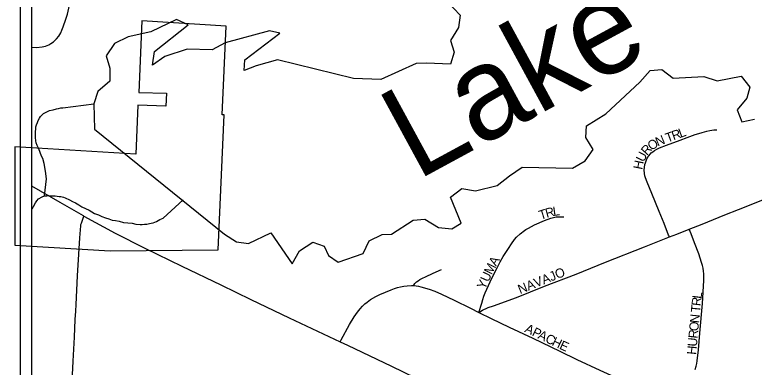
# Model space of a CAD drawing. Extents: x -5.4 to 49.9, y 13.2 to 48.4.
# Drawn here: x 26.26 to 27.015, y 42.652 to 43.012 of the extents above; entities that cross this region are included whole.
import ezdxf

# ---------------------------------------------------------------- set-up
doc = ezdxf.new("R2010")
doc.units = 0
for name, color, linetype in [('GM_X_Corporation', 7, 'Continuous'), ('GM_X_County_Road', 7, 'Continuous'), ('GM_X_Major_Lake', 7, 'Continuous'), ('GM_X_Major_Lake_Text', 7, 'Continuous'), ('GM_X_Major_River', 7, 'Continuous'), ('GM_X_Township', 7, 'Continuous'), ('GM_X_Township_Road', 7, 'Continuous'), ('GM_X_Township_Subdivision', 7, 'Continuous'), ('GM_X_Township_Subdivision_Text', 7, 'Continuous')]:
    doc.layers.add(name, color=color, linetype=linetype)

msp = doc.modelspace()

# ---------------------------------------------------------------- linework, layer by layer
at = {"layer": 'GM_X_Corporation'}
for p, q in [((26.26551, 43.78252), (26.26551, 42.05419)), ((26.25991, 42.87737), (26.25991, 42.77689))]:
    msp.add_line(p, q, dxfattribs=at)
msp.add_lwpolyline([(26.25991, 42.77689), (26.3573, 42.77098), (26.46771, 42.772), (26.47367, 42.91013), (26.47177, 42.91025), (26.47569, 43.00088), (26.38967, 43.0061), (26.38652, 42.93306), (26.41492, 42.93233), (26.41435, 42.91909), (26.38576, 42.91982), (26.3836, 42.86986), (26.25991, 42.87737)], dxfattribs=at)
at = {"layer": 'GM_X_County_Road'}
for points in [[(26.2771, 42.83744), (26.30605, 42.82085), (26.32962, 42.807), (26.33059, 42.80647)], [(26.33059, 42.80647), (26.36234, 42.78919), (26.39264, 42.77368), (26.43071, 42.75545), (26.47045, 42.73637), (26.5011, 42.72131), (26.54035, 42.70261), (26.59236, 42.67796)], [(26.59236, 42.67796), (26.59986, 42.6744), (26.64477, 42.65311), (26.6945, 42.62894), (26.73983, 42.6071), (26.78075, 42.58757), (26.80831, 42.57462), (26.83401, 42.56232), (26.85936, 42.55058), (26.87388, 42.54353), (26.90078, 42.53072), (26.9225, 42.51997), (26.93923, 42.51181), (26.97405, 42.49539), (27.03132, 42.46825), (27.06275, 42.45329), (27.11662, 42.42769), (27.1357, 42.41862), (27.15695, 42.4083), (27.18263, 42.39579), (27.20393, 42.38562), (27.21459, 42.38058), (27.23308, 42.37173), (27.23815, 42.36925)]]:
    msp.add_lwpolyline(points, dxfattribs=at)
at = {"layer": 'GM_X_Major_Lake'}
for points in [[(26.69535, 43.03297), (26.71498, 43.01205), (26.71318, 42.99956), (26.70492, 42.98608), (26.70883, 42.97424), (26.70514, 42.9618), (26.68053, 42.9631), (26.6699, 42.96257), (26.6339, 42.94629), (26.60587, 42.94728), (26.5282, 42.96645), (26.50645, 42.9601)], [(26.50645, 42.9601), (26.49421, 42.95544), (26.49484, 42.96643), (26.5307, 42.99372), (26.52013, 42.99585), (26.47475, 42.98357), (26.4617, 42.97664), (26.43594, 42.97721), (26.41302, 42.96975), (26.40069, 42.96091), (26.40252, 42.97491), (26.43687, 43.00224), (26.42524, 43.00743), (26.3988, 42.99511), (26.37556, 42.98993), (26.36176, 42.98302), (26.35313, 42.97031), (26.35702, 42.9577), (26.35711, 42.94442), (26.34474, 42.93407), (26.34067, 42.92125), (26.34123, 42.89544)], [(26.47418, 42.78815), (26.48652, 42.78029), (26.49861, 42.77851), (26.5216, 42.78938), (26.54326, 42.75779), (26.55076, 42.77091), (26.56422, 42.77972), (26.57588, 42.77567), (26.58022, 42.76608), (26.59031, 42.75941), (26.61591, 42.76833), (26.62188, 42.78111), (26.63529, 42.78764), (26.64478, 42.78819), (26.66671, 42.80251), (26.67886, 42.80338), (26.6927, 42.79473), (26.70632, 42.79367), (26.71592, 42.79915), (26.70514, 42.82595), (26.71671, 42.8348), (26.73068, 42.83222), (26.7528, 42.8378), (26.76515, 42.84777), (26.77824, 42.85659), (26.82977, 42.85546), (26.84245, 42.86315), (26.85067, 42.87473), (26.84336, 42.88704), (26.84401, 42.89879), (26.86362, 42.91126), (26.89846, 42.9435), (26.90896, 42.95541), (26.92073, 42.95629), (26.93229, 42.94769), (26.96379, 42.94928), (26.97734, 42.9448), (27.00209, 42.94957), (27.01094, 42.93837), (27.00765, 42.92706), (26.99791, 42.91513), (27.00256, 42.90289), (27.01552, 42.90564)], [(26.34123, 42.89544), (26.47418, 42.78815)]]:
    msp.add_lwpolyline(points, dxfattribs=at)
at = {"layer": 'GM_X_Major_River'}
for points in [[(26.29028, 42.82711), (26.29236, 42.84456), (26.29131, 42.85255), (26.28987, 42.86016), (26.28841, 42.86549), (26.28729, 42.86778), (26.28581, 42.8716), (26.28434, 42.87541), (26.28285, 42.87884), (26.28174, 42.88151), (26.28138, 42.88342), (26.28104, 42.88684), (26.28108, 42.89064), (26.28154, 42.89785), (26.28194, 42.89974), (26.2831, 42.90239), (26.28388, 42.90428), (26.28504, 42.90655), (26.2862, 42.90843), (26.28927, 42.91144), (26.29194, 42.91293), (26.29537, 42.91441), (26.29917, 42.91513), (26.3026, 42.91624), (26.3045, 42.9166), (26.30679, 42.91733), (26.30906, 42.91731), (26.34067, 42.92125)], [(26.2771, 42.81344), (26.27762, 42.81395), (26.27916, 42.81621), (26.2811, 42.81999), (26.28226, 42.82226), (26.28418, 42.82414), (26.288, 42.82638), (26.29028, 42.82711), (26.29256, 42.82709), (26.29484, 42.82744), (26.29674, 42.82742), (26.29901, 42.8274), (26.30129, 42.82738), (26.30318, 42.82698), (26.30508, 42.82658), (26.30698, 42.82656), (26.30962, 42.82577), (26.31152, 42.82537), (26.31567, 42.82305), (26.31869, 42.8215), (26.32209, 42.81994), (26.32548, 42.81801), (26.3285, 42.81608), (26.33605, 42.81258), (26.33869, 42.81103), (26.34133, 42.80911), (26.34549, 42.80792), (26.34888, 42.80599), (26.35267, 42.80481), (26.35607, 42.80363), (26.35947, 42.80246), (26.36288, 42.80204), (26.36667, 42.80124), (26.37083, 42.80006), (26.37538, 42.79963), (26.37993, 42.79921), (26.38372, 42.79841), (26.38789, 42.79798), (26.39017, 42.79796), (26.39245, 42.79832), (26.39473, 42.79829), (26.39739, 42.79902), (26.39929, 42.79938), (26.40119, 42.79974), (26.40462, 42.80085), (26.40806, 42.80309), (26.41149, 42.80457), (26.43189, 42.82302)]]:
    msp.add_lwpolyline(points, dxfattribs=at)
at = {"layer": 'GM_X_Township'}
msp.add_line((26.2771, 45.17828), (26.2771, 40.9761), dxfattribs=at)
at = {"layer": 'GM_X_Township_Road'}
msp.add_lwpolyline([(26.31821, 42.63066), (26.31961, 42.65817), (26.32089, 42.68277), (26.32174, 42.70074), (26.32218, 42.70939), (26.32246, 42.71621), (26.32407, 42.7453), (26.32545, 42.76759), (26.32641, 42.78432), (26.32731, 42.79668), (26.32753, 42.79794), (26.3279, 42.79929), (26.3287, 42.80145), (26.33059, 42.80647)], dxfattribs=at)
at = {"layer": 'GM_X_Township_Subdivision'}
for points in [[(26.2771, 42.97921), (26.28218, 42.97904), (26.28775, 42.97953), (26.29143, 42.98024), (26.29461, 42.98155), (26.29686, 42.98296), (26.29939, 42.98474), (26.30262, 42.9877), (26.30495, 42.99061), (26.30681, 42.99381), (26.30802, 42.99655), (26.30943, 43.00012), (26.31204, 43.00779), (26.31363, 43.01314), (26.31522, 43.0191), (26.31741, 43.02987), (26.31917, 43.03853), (26.32038, 43.04651), (26.32044, 43.0478)], [(26.94884, 42.7932), (26.96214, 42.79844), (26.98522, 42.80767), (26.99906, 42.81317), (27.02072, 42.82186), (27.04399, 42.83121), (27.09353, 42.85109), (27.12002, 42.86175), (27.17718, 42.88426), (27.21402, 42.89898), (27.24043, 42.90974), (27.25551, 42.91543), (27.26198, 42.91745), (27.26863, 42.91947), (27.27533, 42.92107), (27.2822, 42.92214), (27.28907, 42.92279)], [(26.9286, 42.78517), (26.92783, 42.78717), (26.92314, 42.79896), (26.91819, 42.81137), (26.91067, 42.82969), (26.9058, 42.84111), (26.90419, 42.84581), (26.90366, 42.84784), (26.90322, 42.85004), (26.90292, 42.85375), (26.90308, 42.85638), (26.90358, 42.85943), (26.90406, 42.86107), (26.90481, 42.86312), (26.90571, 42.8651), (26.90662, 42.86674), (26.90763, 42.8683), (26.90884, 42.8697), (26.91004, 42.87112), (26.91155, 42.87241), (26.91347, 42.87373), (26.91583, 42.87513), (26.91834, 42.87648), (26.92563, 42.87916), (26.93966, 42.88433), (26.94672, 42.88693), (26.95485, 42.88992), (26.95873, 42.89107), (26.96225, 42.89216), (26.96681, 42.89335), (26.96981, 42.89403), (26.97406, 42.89471), (26.97713, 42.89475)], [(26.73404, 42.70811), (26.73692, 42.71752), (26.73791, 42.72132), (26.73897, 42.72463), (26.74028, 42.72798), (26.74538, 42.73934), (26.75082, 42.75049), (26.7525, 42.75379), (26.75571, 42.75974), (26.75889, 42.76505), (26.76293, 42.77131), (26.76435, 42.77335), (26.76729, 42.77807), (26.7704, 42.78265), (26.77244, 42.78499), (26.77606, 42.7884), (26.78056, 42.7917), (26.7821, 42.79269), (26.7847, 42.79433), (26.79077, 42.79743), (26.80102, 42.80194), (26.80743, 42.80433), (26.81284, 42.80567), (26.81592, 42.80585), (26.81899, 42.8058), (26.8202, 42.80578), (26.82078, 42.80564)], [(26.9286, 42.78517), (26.93615, 42.78819), (26.94884, 42.7932)], [(26.95504, 42.64957), (26.95595, 42.653), (26.95652, 42.65581), (26.95694, 42.6585), (26.95818, 42.66961), (26.95964, 42.68694), (26.96234, 42.71725), (26.96394, 42.7408), (26.96392, 42.74442), (26.96377, 42.74762), (26.9635, 42.75018), (26.96305, 42.75317), (26.96243, 42.75618), (26.96153, 42.75918), (26.95864, 42.76804), (26.95436, 42.77904), (26.95075, 42.78831), (26.94884, 42.7932)], [(26.73404, 42.70811), (26.73481, 42.70856), (26.73778, 42.71025), (26.73916, 42.71104), (26.74151, 42.71216), (26.74362, 42.71296), (26.74908, 42.71493), (26.77235, 42.72322), (26.80112, 42.73476), (26.83348, 42.7473), (26.86342, 42.75936), (26.90327, 42.77508), (26.9286, 42.78517)], [(26.66737, 42.73546), (26.66755, 42.73577), (26.66867, 42.73776), (26.66945, 42.73858), (26.6704, 42.73935), (26.672, 42.74048), (26.67369, 42.74162), (26.67497, 42.74233), (26.67649, 42.7431), (26.6793, 42.74446), (26.6872, 42.74827), (26.6958, 42.75207)], [(26.59236, 42.67796), (26.59338, 42.67985), (26.6018, 42.69556), (26.60662, 42.70363), (26.60987, 42.70822), (26.61257, 42.71168), (26.61513, 42.71444), (26.61765, 42.7168), (26.61983, 42.71866), (26.62339, 42.72131), (26.62858, 42.72429), (26.63279, 42.72636), (26.63846, 42.72876), (26.64428, 42.73122), (26.64787, 42.73251), (26.65077, 42.73341), (26.65394, 42.73422), (26.65735, 42.73481), (26.66078, 42.7353), (26.66521, 42.73558), (26.66737, 42.73546)], [(26.66737, 42.73546), (26.66992, 42.73522), (26.67246, 42.73477), (26.67466, 42.73433), (26.68306, 42.73195), (26.68883, 42.72971), (26.69585, 42.72673), (26.70863, 42.7204), (26.72548, 42.71245), (26.73404, 42.70811)], [(26.73404, 42.70811), (26.74654, 42.70177), (26.76507, 42.69304), (26.78927, 42.68167), (26.81669, 42.66842), (26.83398, 42.66002), (26.85763, 42.64911), (26.86881, 42.64375), (26.88844, 42.63433), (26.92416, 42.61719), (26.93697, 42.61118)]]:
    msp.add_lwpolyline(points, dxfattribs=at)

# ---------------------------------------------------------------- texts
at = {"layer": 'GM_X_Major_Lake_Text'}
msp.add_text('Lake', height=0.094691, rotation=28.51356, dxfattribs=at).set_placement((26.67048, 42.84241))
at = {"layer": 'GM_X_Township_Subdivision_Text'}
for s, rotation, p in [('L', 19.99701, (26.9399, 42.88649)), ('N', 22.77958, (26.91667, 42.87759)), ('T', 19.99011, (26.92658, 42.88165)), ('R', 19.98471, (26.93285, 42.88393)), ('O', 33.81736, (26.91017, 42.87318)), ('R', 48.53991, (26.90569, 42.86798)), ('U', 63.00489, (26.90226, 42.86108)), ('H', 78.33424, (26.90079, 42.85355)), ('T', 17.91645, (26.797, 42.80263)), ('R', 15.38503, (26.80324, 42.80465)), ('L', 8.06054, (26.81016, 42.80658)), ('A', 60.37438, (26.75152, 42.75473)), ('M', 63.06845, (26.74705, 42.74591)), ('NAVAJO', 21.99029, (26.77609, 42.72677)), ('U', 65.31186, (26.74361, 42.73843)), ('Y', 65.31186, (26.74013, 42.73086)), ('R', 83.50156, (26.96049, 42.71418)), ('L', 82.46493, (26.96133, 42.72159)), ('T', 84.62981, (26.95987, 42.70759)), ('N', 84.63737, (26.95885, 42.69681)), ('A', 334.02158, (26.78004, 42.68838)), ('P', 334.00923, (26.78753, 42.68473)), ('O', 84.63123, (26.95807, 42.68851)), ('A', 334.02909, (26.79353, 42.68181)), ('C', 334.0105, (26.80102, 42.67816)), ('R', 84.62528, (26.95737, 42.68104)), ('H', 334.02909, (26.80777, 42.67487)), ('E', 335.54004, (26.81551, 42.67111)), ('U', 84.63123, (26.95659, 42.67274)), ('H', 84.63737, (26.95581, 42.66445))]:
    msp.add_text(s, height=0.00947, rotation=rotation, dxfattribs=at).set_placement(p)

doc.saveas('drawing.dxf')
